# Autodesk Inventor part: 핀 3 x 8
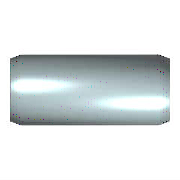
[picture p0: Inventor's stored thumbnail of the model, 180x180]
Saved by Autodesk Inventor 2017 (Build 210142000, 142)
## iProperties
IsCustomPart: 1
Created: 2012-02
Part Number: 핀 3 x 8
Material: 강철, 연강
Description: 평행 핀
Document SubType Name: Modeling
Standard: KS B 1320
Designer: mduedu
Standards Organization: KS
Language: ko-KR
Size Designation: B 3 x  8
Categories: <MemberInstance><Categories><Category DisplayName="조임쇠" InternalName="e4da775c-781d-43d5-af7c-5136215cf5a6" Mnemonic="FSTN"><Category DisplayName="핀" InternalNa
Density: 1 g/cm^3
Appearance: 노란색
Author: mduedu
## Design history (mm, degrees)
sketch "스케치"
  geometry: C1 r 1.5 at (0, 0); 1 further point
  constraints: 1 centre point, 1 coincident
  dimensions: "d1" = 3 diameter of C1 (= NND)
extrude "본체" new body sketch "스케치" distance "d2" = 8 (= NLG); taper "d3" = 0 deg
chamfer "스케치2" distance "d8" = 0.5 (= PHH); stored, may be unused: angle "d9" = 15 deg (= FAWI), second distance "d12" = 0.5 (= PHH)
body "Solid1"
chamfer "모따기1" distance "d4" = 0.5 (= PHH); stored, may be unused: angle "d5" = 15 deg (= FAWI), second distance "d11" = 0.5 (= PHH)
other parameters: "NND" = 3 [user parameter; used in 1 equation term], "NLG" = 8 [user parameter; used in 1 equation term], "PHH" = 0.5 [user parameter; used in 4 equation terms], "FAWI" = 15 deg [user parameter; used in 2 equation terms], "d13" = 0, "d15" = 0, "d16" = 0, "KAH" = 0.4 [user parameter]
